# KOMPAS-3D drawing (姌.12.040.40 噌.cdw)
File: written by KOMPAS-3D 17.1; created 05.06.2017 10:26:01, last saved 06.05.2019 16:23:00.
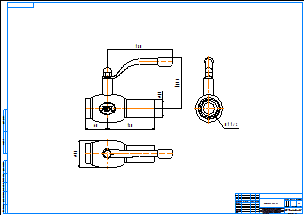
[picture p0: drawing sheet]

Sheet 1: A1, landscape

Title block, sheet 1: name: КШ.12.040.40 рс; material: Внимание! Данный продукт является объектом авторского права ООО «Торговый Дом АДЛ». / Запрещается изменение, копирование, распространение / (в том числе путем копирования на другие сайты и ресурсы в Интернете) / или любое иное использование информации и объектов без предварительного / согласия правообладателя (ООО «Торговый Дом АДЛ»).; sheets: 1; organisation: ООО "Торговый дом АДЛ"; sheet format: A1; stored path: C:\Users\kka\KOMPAS_Work\Модели кранов для исследований\Все краники\Редуцированный резьба-сварка ШК БИВАЛ\КШ.02.015.40 рс.cdw

Views: Вид 1, Проекционный вид 2, Проекционный вид 3
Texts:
  Klimkovich
  ADL
Dimensions and other numbers on the sheet: 180; 48; 130; 60; 142,6; 76; 1:1; 1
